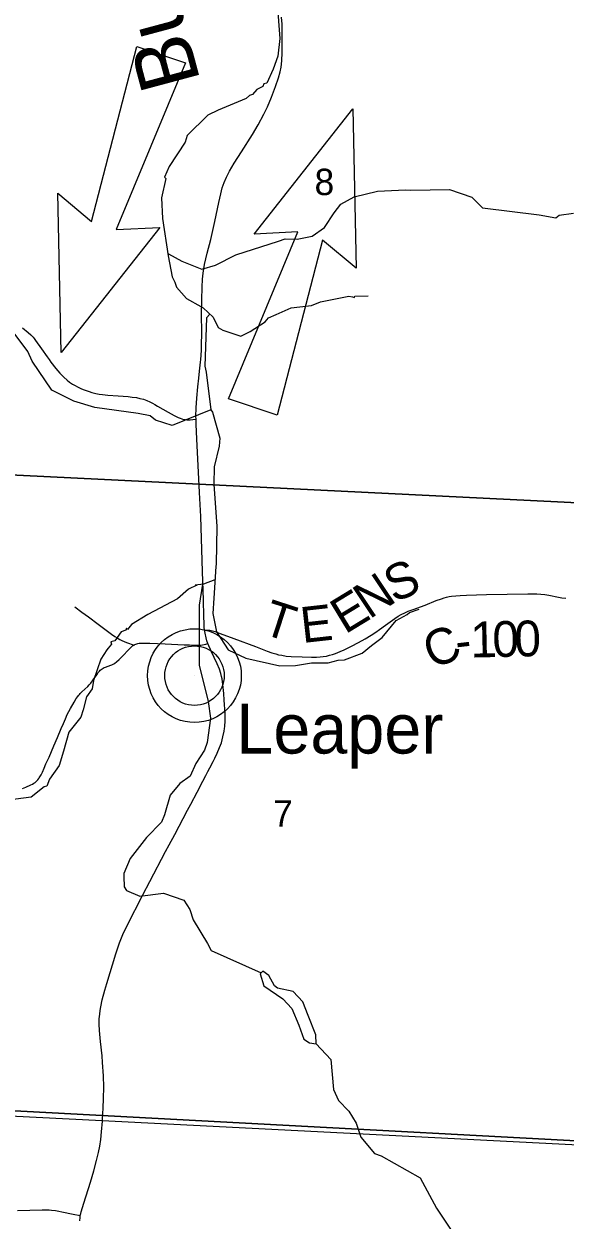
# Model space of a CAD drawing. Extents: x 396.2 to 468.4, y 232.6 to 279.1.
# Drawn here: x 419.533 to 420.393, y 270.146 to 272.044 of the extents above; entities that cross this region are included whole.
import ezdxf

# ---------------------------------------------------------------- set-up
doc = ezdxf.new("R2010")
doc.units = 0
for name, color, linetype in [('Default', 7, 'Continuous'), ('GM_X_County_Road', 7, 'Continuous'), ('GM_X_County_Road_Text', 7, 'Continuous'), ('GM_X_Minor_River', 7, 'Continuous'), ('GM_X_Minor_River_Text', 7, 'Continuous'), ('GM_X_Section', 7, 'Continuous'), ('GM_X_Section_Text', 7, 'Continuous'), ('GM_X_State_Route', 7, 'Continuous'), ('GM_X_Township', 7, 'Continuous'), ('GM_X_Township_Road', 7, 'Continuous'), ('GM_X_Unincorporated', 7, 'Continuous'), ('GM_X_Unincorporated_Location', 7, 'Continuous'), ('GM_X_Unincorporated_Text', 7, 'Continuous'), ('TX_P_1', 7, 'Continuous')]:
    doc.layers.add(name, color=color, linetype=linetype)

msp = doc.modelspace()

# ---------------------------------------------------------------- linework, layer by layer
at = {"layer": 'Default'}
msp.add_lwpolyline([(420.4241, 270.2645), (419.658, 270.3039), (418.8718, 270.3435), (418.5989, 270.3564), (417.8712, 270.3927), (416.2596, 270.4764), (415.4605, 270.5176), (415.2459, 270.5284), (415.1765, 269.4523), (415.0934, 268.0402), (415.0582, 267.4588), (415.0293, 266.9964)], dxfattribs=at)
at = {"layer": 'GM_X_County_Road'}
for points in [[(419.5315, 271.5616), (419.5401, 271.5544), (419.5443, 271.5507), (419.5465, 271.5487), (419.5482, 271.5467), (419.5499, 271.5447), (419.5521, 271.5417), (419.5612, 271.5287), (419.5702, 271.5159), (419.5734, 271.5114), (419.5764, 271.5074), (419.5844, 271.4971), (419.5903, 271.4899), (419.5942, 271.4859), (419.5969, 271.4833), (419.602, 271.4788), (419.6059, 271.4758), (419.6105, 271.4726), (419.6148, 271.4701), (419.6186, 271.468), (419.6237, 271.4656), (419.6277, 271.464), (419.6324, 271.4622), (419.6373, 271.4606), (419.6414, 271.4594), (419.6479, 271.4577), (419.6528, 271.4567), (419.6583, 271.4559), (419.6669, 271.4551), (419.6829, 271.4539), (419.6989, 271.4527), (419.7056, 271.452), (419.7122, 271.4511), (419.7178, 271.4499), (419.7235, 271.4484), (419.7286, 271.4465), (419.7332, 271.4445), (419.7376, 271.4422), (419.7415, 271.4401), (419.7458, 271.4377), (419.7624, 271.428), (419.7719, 271.4229), (419.7783, 271.4195), (419.7814, 271.4182), (419.7843, 271.4172), (419.7871, 271.4165), (419.7899, 271.4161), (419.7921, 271.4159), (419.7946, 271.4158), (419.7976, 271.416), (419.8018, 271.4163), (419.8068, 271.4166)], [(419.8205, 271.0824), (419.8247, 271.0821), (419.8286, 271.0819), (419.8308, 271.0816), (419.8331, 271.0811), (419.8373, 271.0798), (419.8453, 271.0769), (419.8666, 271.069), (419.901, 271.056), (419.9199, 271.0489), (419.9272, 271.0463), (419.9334, 271.0444), (419.938, 271.0432), (419.9429, 271.0422), (419.95, 271.0411), (419.9576, 271.0405), (419.9754, 271.0396), (419.9903, 271.0395), (419.9981, 271.0395), (420.004, 271.0397), (420.0087, 271.0402), (420.0138, 271.0411), (420.0187, 271.0423), (420.0234, 271.0436), (420.0285, 271.0453), (420.0354, 271.0482), (420.0418, 271.0511), (420.0539, 271.0569), (420.065, 271.0625), (420.0751, 271.0681), (420.085, 271.0741), (420.0924, 271.0789), (420.0983, 271.0831), (420.1078, 271.09), (420.1151, 271.0955), (420.1223, 271.1008), (420.1276, 271.1042), (420.1325, 271.107), (420.1381, 271.1098), (420.1438, 271.1122), (420.1514, 271.115), (420.1708, 271.122), (420.1883, 271.1291), (420.1965, 271.132), (420.2007, 271.1334), (420.2045, 271.1346), (420.2085, 271.1354), (420.2125, 271.1361), (420.2193, 271.1367), (420.2263, 271.1371), (420.2365, 271.1376), (420.2679, 271.1385), (420.301, 271.1393), (420.3339, 271.1399), (420.3415, 271.1398), (420.3477, 271.1396), (420.3542, 271.1393), (420.3605, 271.1387), (420.3668, 271.1378), (420.3821, 271.1344), (420.3879, 271.1335), (420.3938, 271.1328)], [(419.5577, 270.8476), (419.5589, 270.8494), (419.5607, 270.8527), (419.5628, 270.8569), (419.5655, 270.8634), (419.5684, 270.8703), (419.5735, 270.8807), (419.5812, 270.8987), (419.5867, 270.9118), (419.5927, 270.926), (419.5961, 270.934), (419.5993, 270.9414), (419.6024, 270.9481), (419.6075, 270.958), (419.6131, 270.9677), (419.6167, 270.9735), (419.6191, 270.977), (419.6203, 270.9787), (419.6216, 270.9802), (419.6229, 270.9818), (419.6243, 270.9831), (419.6256, 270.9843), (419.6349, 270.9929), (419.6373, 270.9954), (419.6398, 270.9982), (419.6435, 271.0031), (419.6491, 271.0113), (419.6516, 271.0148), (419.6535, 271.0172), (419.6548, 271.0187), (419.6562, 271.0199), (419.6576, 271.0209), (419.6592, 271.022), (419.6609, 271.0228), (419.6628, 271.0236), (419.6716, 271.0264), (419.6733, 271.0271), (419.6751, 271.028), (419.6764, 271.0289), (419.6777, 271.0298), (419.6807, 271.032), (419.6847, 271.0356), (419.6885, 271.0392), (419.6915, 271.0423), (419.6983, 271.0496), (419.7025, 271.0541), (419.7043, 271.0557), (419.7061, 271.0571), (419.7084, 271.0585)], [(419.7084, 271.0585), (419.7095, 271.0592), (419.7111, 271.0601), (419.7128, 271.0606), (419.7145, 271.0611), (419.7167, 271.0615), (419.7199, 271.0617), (419.7267, 271.0617), (419.7335, 271.0614), (419.7579, 271.0602), (419.788, 271.059), (419.7966, 271.0587), (419.8079, 271.0582), (419.8111, 271.0582), (419.8142, 271.0583), (419.8173, 271.0586), (419.8198, 271.0592), (419.8222, 271.06), (419.8257, 271.0611)], [(419.5315, 270.8311), (419.5363, 270.8331), (419.5443, 270.8365), (419.5471, 270.8379), (419.5494, 270.8392), (419.5515, 270.8407), (419.5535, 270.8426), (419.5554, 270.8445), (419.5571, 270.8468), (419.5577, 270.8476)]]:
    msp.add_lwpolyline(points, dxfattribs=at)
at = {"layer": 'GM_X_Minor_River'}
for points in [[(419.9355, 272.0761), (419.9397, 272.021), (419.9367, 271.9929), (419.9292, 271.9719), (419.9194, 271.9499), (419.9145, 271.9487), (419.913, 271.9445), (419.9035, 271.9399), (419.8963, 271.9319), (419.8918, 271.9304), (419.8865, 271.9255), (419.8419, 271.9071), (419.8253, 271.8991), (419.7925, 271.8667), (419.7894, 271.8564), (419.7642, 271.8176), (419.7566, 271.8008), (419.7589, 271.7989), (419.7521, 271.7678), (419.7537, 271.7351), (419.7624, 271.6762), (419.7689, 271.6427), (419.773, 271.6344), (419.7757, 271.6264), (419.7916, 271.6082), (419.8143, 271.5957), (419.8181, 271.5934), (419.834, 271.5786), (419.8419, 271.5623), (419.8495, 271.5578), (419.8779, 271.5487), (419.893, 271.556), (419.9168, 271.5712), (419.9217, 271.5777), (419.9338, 271.5827), (419.9576, 271.5934), (419.9904, 271.5972), (420.0044, 271.603), (420.0494, 271.6122), (420.0551, 271.6111), (420.0585, 271.6099), (420.0592, 271.6122), (420.08, 271.6123)], [(419.763, 271.6791), (419.7842, 271.6677), (419.8159, 271.6549), (419.8377, 271.6614), (419.8699, 271.6775), (419.9375, 271.6993), (419.9485, 271.7031), (419.9674, 271.7025), (419.991, 271.707), (420.0107, 271.7208), (420.0261, 271.7443), (420.0368, 271.758), (420.0579, 271.7698), (420.0948, 271.7785), (420.1395, 271.7805), (420.1478, 271.7799), (420.2094, 271.781), (420.245, 271.7692), (420.2615, 271.752), (420.3515, 271.7411), (420.3782, 271.7365), (420.3836, 271.7405), (420.406, 271.7435)], [(419.8285, 271.5837), (419.8234, 271.5778), (419.8206, 271.5009)], [(419.8303, 271.4315), (419.7691, 271.4069), (419.7425, 271.4153), (419.7337, 271.4224), (419.7149, 271.4261), (419.646, 271.4355), (419.613, 271.4453), (419.5777, 271.4627), (419.5466, 271.5089), (419.5395, 271.5243), (419.5071, 271.5679)], [(419.8206, 271.5009), (419.8231, 271.4912), (419.8303, 271.4315), (419.833, 271.4281), (419.8448, 271.3867), (419.8436, 271.3741), (419.8357, 271.341), (419.835, 271.3137), (419.84, 271.2468), (419.8386, 271.1867), (419.8382, 271.1833), (419.8348, 271.1327), (419.8333, 271.1087), (419.8394, 271.0795), (419.858, 271.051), (419.886, 271.0378), (419.9397, 271.0257), (419.9646, 271.0262), (419.9903, 271.0304), (420.0164, 271.0305), (420.0323, 271.0347), (420.0428, 271.0351), (420.0708, 271.0454), (420.0855, 271.058), (420.1022, 271.0706), (420.1244, 271.0973), (420.1418, 271.1068), (420.1456, 271.1102), (420.1611, 271.1152)], [(419.8368, 271.1621), (419.8185, 271.1551), (419.8053, 271.1535), (419.808, 271.1535), (419.7947, 271.1471), (419.7774, 271.1318), (419.7301, 271.107), (419.7041, 271.091), (419.698, 271.0833), (419.6965, 271.0852), (419.6954, 271.0822), (419.6878, 271.0795), (419.678, 271.0654), (419.6716, 271.0635), (419.6727, 271.0601), (419.6671, 271.0536), (419.6652, 271.051), (419.6557, 271.0361), (419.6441, 271.0022), (419.6418, 270.9889), (419.6331, 270.9764), (419.6275, 270.9558), (419.6237, 270.944), (419.6048, 270.9204), (419.5966, 270.89), (419.5894, 270.8672), (419.5739, 270.8455), (419.5698, 270.8348), (419.5656, 270.8333), (419.5448, 270.8173), (419.5086, 270.8126)], [(419.817, 271.1549), (419.8119, 271.1218), (419.8119, 271.0595), (419.8117, 271.0268), (419.8258, 270.969), (419.8296, 270.9427), (419.8243, 270.9038), (419.8201, 270.8918), (419.8066, 270.8705), (419.7973, 270.8507), (419.7811, 270.8387), (419.7658, 270.8202), (419.7569, 270.789), (419.752, 270.7773), (419.7282, 270.753), (419.7023, 270.7197), (419.6921, 270.6961), (419.692, 270.6912), (419.6926, 270.6748), (419.6966, 270.669), (419.7175, 270.6603), (419.755, 270.6648), (419.7872, 270.6536), (419.797, 270.6388), (419.8022, 270.6227), (419.8252, 270.5851), (419.8309, 270.5739), (419.9104, 270.5386)], [(419.9143, 270.5177), (419.9446, 270.4974), (419.9589, 270.4821), (419.9698, 270.4552), (419.9779, 270.4333), (419.9871, 270.4273), (419.9973, 270.4258), (419.997, 270.4403), (419.9847, 270.4707), (419.9763, 270.4926), (419.9609, 270.509), (419.9361, 270.5144), (419.9313, 270.5179), (419.9223, 270.5342), (419.9131, 270.5409), (419.9084, 270.5369), (419.9143, 270.5177)], [(419.9973, 270.4258), (420.0211, 270.4012), (420.0253, 270.3532), (420.0331, 270.3358), (420.0496, 270.319), (420.0611, 270.3), (420.0684, 270.2778), (420.0903, 270.2516), (420.1006, 270.2482)], [(420.1006, 270.2482), (420.1625, 270.2133), (420.1886, 270.1652), (420.2139, 270.1269), (420.234, 270.0735), (420.2443, 270.0026), (420.2505, 269.9768), (420.2582, 269.9605)]]:
    msp.add_lwpolyline(points, dxfattribs=at)
at = {"layer": 'GM_X_Section'}
for points in [[(419.5162, 272.3211), (420.0191, 272.3027), (420.5671, 272.2854), (420.4987, 271.28), (419.4571, 271.3312), (419.4827, 271.7399), (419.5072, 272.1445)], [(419.4571, 271.3312), (420.4987, 271.28), (420.43, 270.2709), (419.3993, 270.3259)], [(419.3993, 270.3259), (420.43, 270.2709), (420.3647, 269.2542), (419.3283, 269.3066)]]:
    msp.add_lwpolyline(points, close=True, dxfattribs=at)
at = {"layer": 'GM_X_State_Route'}
for points in [[(419.6582, 270.3034), (419.6585, 270.3067), (419.6593, 270.3236), (419.6601, 270.3392), (419.6602, 270.3572), (419.6597, 270.3752), (419.6585, 270.3963), (419.6576, 270.407), (419.655, 270.4294), (419.6535, 270.4472), (419.6531, 270.457), (419.6532, 270.4653), (419.6538, 270.473), (419.6545, 270.4788), (419.6556, 270.4847), (419.658, 270.4958), (419.662, 270.5112), (419.665, 270.5217), (419.6793, 270.5684), (419.6853, 270.586), (419.6906, 270.5992), (419.6973, 270.6138), (419.7225, 270.6624), (419.7332, 270.6833), (419.7585, 270.7311), (419.7641, 270.7417), (419.7729, 270.758), (419.7933, 270.7963), (419.7987, 270.8061), (419.8088, 270.8253), (419.8178, 270.8423), (419.8225, 270.8517), (419.8256, 270.8578), (419.8287, 270.8638), (419.8339, 270.8736), (419.8367, 270.8791), (419.8404, 270.8869), (419.8443, 270.896), (419.8458, 270.8998), (419.847, 270.9035), (419.8494, 270.9127), (419.8515, 270.9218), (419.8521, 270.9259), (419.8525, 270.9293), (419.8532, 270.9382), (419.853, 270.9499), (419.8517, 270.971), (419.8508, 270.9816), (419.8494, 270.9957), (419.8488, 271.0004), (419.8481, 271.0051), (419.8473, 271.0087), (419.8461, 271.0134), (419.8438, 271.0204), (419.8403, 271.0288), (419.831, 271.0487), (419.8297, 271.0515), (419.8272, 271.0571), (419.8257, 271.0611), (419.8241, 271.0654), (419.8227, 271.07), (419.8212, 271.0771), (419.8205, 271.0824), (419.8199, 271.0866), (419.8195, 271.0922), (419.8193, 271.1044), (419.8186, 271.1296), (419.8173, 271.1751), (419.8142, 271.2622), (419.8123, 271.3007), (419.8078, 271.3856), (419.807, 271.4085), (419.8068, 271.4166), (419.8066, 271.4212), (419.8071, 271.4351), (419.808, 271.45), (419.8098, 271.4684), (419.8112, 271.4817), (419.8124, 271.4929), (419.8138, 271.5071), (419.8143, 271.5117), (419.8154, 271.5258), (419.8156, 271.5323), (419.8158, 271.5562), (419.8157, 271.5813), (419.816, 271.606), (419.8164, 271.6261), (419.817, 271.6388), (419.8181, 271.6487), (419.8205, 271.6621), (419.8247, 271.6802), (419.8301, 271.7019), (419.8366, 271.7304), (419.843, 271.7608), (419.846, 271.7741), (419.8485, 271.7836), (419.8515, 271.7924), (419.855, 271.8009), (419.8601, 271.8105), (419.8675, 271.8228), (419.879, 271.8412), (419.8964, 271.8686), (419.9052, 271.8837), (419.9143, 271.9007), (419.9202, 271.9126), (419.9267, 271.9277), (419.9332, 271.9446), (419.9378, 271.9582), (419.9406, 271.9681), (419.9421, 271.9755), (419.9431, 271.9851), (419.9436, 271.9984), (419.9438, 272.0266), (419.9434, 272.0433), (419.9424, 272.0544)], [(419.623, 270.1535), (419.6237, 270.1566), (419.6245, 270.1595), (419.6287, 270.1733), (419.6392, 270.2064), (419.6446, 270.2245), (419.6487, 270.2406), (419.6518, 270.2534), (419.6538, 270.2633), (419.6556, 270.2743), (419.6568, 270.2861), (419.6582, 270.3034)], [(419.5235, 270.1616), (419.5626, 270.1627), (419.5662, 270.1627), (419.5699, 270.1626), (419.5737, 270.1623), (419.5773, 270.162), (419.5835, 270.1612), (419.5889, 270.1604), (419.5938, 270.1594), (419.6118, 270.1558), (419.623, 270.1535)], [(419.6224, 270.145), (419.6226, 270.1501), (419.623, 270.1535)]]:
    msp.add_lwpolyline(points, dxfattribs=at)
at = {"layer": 'GM_X_Township'}
msp.add_lwpolyline([(420.4241, 270.2645), (419.658, 270.3039), (418.8718, 270.3435), (418.5989, 270.3564), (417.8712, 270.3927)], dxfattribs=at)
at = {"layer": 'GM_X_Township_Road'}
msp.add_lwpolyline([(419.6141, 271.1192), (419.6253, 271.1109), (419.6358, 271.1031), (419.6513, 271.0918), (419.662, 271.0838), (419.6728, 271.0756), (419.6779, 271.0721), (419.6816, 271.0698), (419.6859, 271.0674), (419.6892, 271.0658), (419.6928, 271.0643), (419.6966, 271.0628), (419.7084, 271.0585)], dxfattribs=at)
at = {"layer": 'GM_X_Unincorporated'}
for radius in [0.0744, 0.0472]:
    msp.add_circle((419.8043, 271.01), radius, dxfattribs=at)
at = {"layer": 'GM_X_Unincorporated_Location'}
msp.add_line((419.8043, 271.01), (419.8043, 271.01), dxfattribs=at)
at = {"layer": 'TX_P_1'}
for p, q in [((419.641, 271.7307), (419.7128, 272.0081)), ((419.7128, 272.0081), (419.7902, 271.9821)), ((419.7902, 271.9821), (419.6798, 271.7178)), ((419.8991, 271.7104), (420.0559, 271.909)), ((420.0559, 271.909), (420.0609, 271.6563)), ((419.5926, 271.5227), (419.5876, 271.7753)), ((419.5876, 271.7753), (419.641, 271.7307)), ((419.7493, 271.7209), (419.5926, 271.5227)), ((419.6798, 271.7178), (419.7493, 271.7209)), ((419.8586, 271.4491), (419.9686, 271.7139)), ((419.9686, 271.7139), (419.8991, 271.7104)), ((420.0076, 271.7008), (419.9357, 271.4234)), ((420.0609, 271.6563), (420.0076, 271.7008)), ((419.9357, 271.4234), (419.8586, 271.4491))]:
    msp.add_line(p, q, dxfattribs=at)

# ---------------------------------------------------------------- texts
at = {"layer": 'GM_X_County_Road_Text'}
for s, rotation, p in [('S', 23.6824, (420.1212, 271.125)), ('N', 33.8168, (420.082, 271.0985)), ('E', 31.3233, (420.0434, 271.0749)), ('T', 341.992, (419.9093, 271.0774)), ('E', 6.3632, (419.9758, 271.0616)), ('C', 21.0284, (420.1813, 271.0201)), ('1', 1.2465, (420.243, 271.0386)), ('0', 1.2387, (420.2779, 271.0393)), ('0', 1.2308, (420.3129, 271.0401)), ('-', 6.6661, (420.2212, 271.036))]:
    msp.add_text(s, height=0.0568, rotation=rotation, dxfattribs=at).set_placement(p)
at = {"layer": 'GM_X_Minor_River_Text'}
msp.add_text('Bullskin', height=0.09471, rotation=105.0011, dxfattribs=at).set_placement((419.8142, 271.9531))
at = {"layer": 'GM_X_Section_Text'}
for s, p in [('8', (419.995, 271.7723)), ('7', (419.9292, 270.7704))]:
    msp.add_text(s, height=0.0419, rotation=0, dxfattribs=at).set_placement(p)
at = {"layer": 'GM_X_Unincorporated_Text'}
msp.add_text('Leaper', height=0.07898, rotation=0, dxfattribs=at).set_placement((419.8708, 270.8864))

doc.saveas('drawing.dxf')
